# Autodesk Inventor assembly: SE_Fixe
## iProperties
Shininess: 64.0
Length Units: 11269
Angle Units: 11279
Time Units: 11290
Mass Units: 11283
Length Display Precision: 3
Angle Display Precision: 2
Compacted: True
Created: 2005-01
Part Number: SE_Fixe
Document SubType Name: Assembly
Designer: Flavien MARTY
Density: 0.0
Volumn: 0.0
Area: 0.0
PropertySet Name: Model Information
Control State: 0
Master: False
Checked Out: False
Author: Flavien MARTY
